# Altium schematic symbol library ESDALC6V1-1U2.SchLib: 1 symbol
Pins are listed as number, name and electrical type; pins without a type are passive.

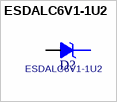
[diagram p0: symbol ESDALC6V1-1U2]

## ESDALC6V1-1U2
designator D?
footprint ST_ST0201
pins: 1 K, 2 A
